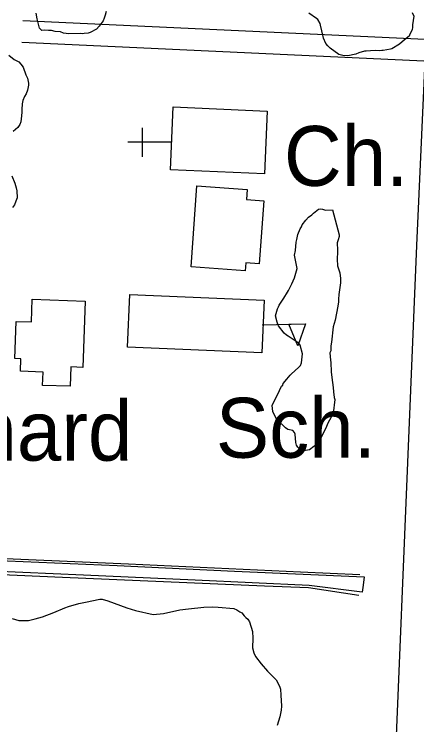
# Model space of a CAD drawing. Extents: x 3677843 to 3715951, y 511991 to 537744.
# Drawn here: x 3693812 to 3694371, y 524461 to 525446 of the extents above; entities that cross this region are included whole.
import ezdxf

# ---------------------------------------------------------------- set-up
doc = ezdxf.new("R2010")
doc.units = 0
for name, color, linetype in [('V-BLDG-IDEN', 7, 'Continuous'), ('V-BLDG-OTLN', 7, 'Continuous'), ('V-ROAD-CNTR', 7, 'Continuous'), ('V-RRAP-FSHR', 7, 'Continuous'), ('V-SITE-OTLN', 7, 'Continuous'), ('V-SITE-OTLN-IDEN', 7, 'Continuous'), ('V-SITE-VEGE', 7, 'Continuous'), ('V-TOPO-SHOR', 7, 'Continuous')]:
    doc.layers.add(name, color=color, linetype=linetype)

msp = doc.modelspace()

# ---------------------------------------------------------------- linework, layer by layer
at = {"layer": 'V-BLDG-OTLN'}
msp.add_line((3694156.62, 525015.2), (3694216.6, 525016.74), dxfattribs=at)
for points in [[(3694057.77, 525095.71), (3694066.02, 525208.25), (3694135.73, 525203.14), (3694134.7, 525189.07), (3694158.62, 525187.32), (3694152.23, 525100), (3694133.94, 525101.34), (3694133.12, 525090.19)], [(3694156.2, 524976.66), (3693969.58, 524984.54), (3693972.66, 525057.48), (3694159.27, 525049.6)], [(3693910.96, 525048.3), (3693907.8, 524956.4), (3693891.08, 524956.97), (3693890.16, 524930.2), (3693851.76, 524931.52), (3693852.39, 524949.92), (3693821.05, 524950.99), (3693821.65, 524968.35), (3693813.3, 524968.64), (3693815.07, 525020.08), (3693836.17, 525019.36), (3693837.26, 525050.83)], [(3694216.6, 525016.74), (3694205.82, 524986.45), (3694193.51, 525016.14)]]:
    msp.add_lwpolyline(points, close=True, dxfattribs=at)
at = {"layer": 'V-ROAD-CNTR'}
for points in [[(3694438.26, 523610.85), (3694392.29, 523695.71), (3694355.89, 523761.39), (3694339.06, 523804.26), (3694326.59, 523855.36), (3694321.7, 523893.17), (3694321.86, 523943.67), (3694324.66, 524023.16), (3694328.91, 524111.65), (3694371.36, 525125.44), (3694418.21, 526169.36), (3694449.93, 526976.4)], [(3694694.4, 525393.26), (3694472.37, 525406.55), (3693824.28, 525436.79)], [(3694692.23, 525363.34), (3694470.78, 525376.6), (3693822.88, 525406.82)]]:
    msp.add_lwpolyline(points, dxfattribs=at)
at = {"layer": 'V-RRAP-FSHR'}
for points in [[(3694291.85, 524668.89), (3694209.71, 524672.61), (3693971.14, 524683.84), (3693746.56, 524693.42), (3693607.22, 524699.07)], [(3693606.63, 524677.46), (3693879.4, 524665.75), (3694159.92, 524653.78), (3694220.73, 524651.43), (3694290.51, 524640.63)]]:
    msp.add_lwpolyline(points, dxfattribs=at)
at = {"layer": 'V-SITE-OTLN'}
for p, q in [((3693989.98, 525288.48), (3693989.98, 525248.48)), ((3694029.98, 525268.48), (3693969.98, 525268.48))]:
    msp.add_line(p, q, dxfattribs=at)
msp.add_lwpolyline([(3694032.91, 525317.4), (3694163.32, 525311.72), (3694159.53, 525224.72), (3694029.12, 525230.41)], close=True, dxfattribs=at)
at = {"layer": 'V-SITE-VEGE'}
for points in [[(3693940.07, 525449.56), (3693938.5, 525444.56), (3693937.45, 525440.68), (3693935.86, 525436.79), (3693930.46, 525429.52), (3693926.67, 525425.04), (3693917.91, 525420.48), (3693915.16, 525419.88), (3693909.65, 525419.24), (3693907.45, 525418.66), (3693904.68, 525419.16), (3693888.13, 525418.88), (3693880.93, 525419.87), (3693876.49, 525421.45), (3693869.31, 525421.88), (3693864.31, 525423.46), (3693859.9, 525423.39), (3693854.92, 525423.86), (3693850.51, 525423.23), (3693847.7, 525426.49), (3693844.17, 525439.69), (3693842.94, 525447.4)], [(3694364.53, 525448.28), (3694366.76, 525443.39), (3694365.22, 525431.38), (3694365.25, 525428.1), (3694364.73, 525424.29), (3694361.51, 525418.26), (3694360.44, 525415.52), (3694353.94, 525410.56), (3694346.9, 525404.5), (3694336.59, 525397.87), (3694334.41, 525397.31), (3694324.61, 525395.59), (3694322.42, 525395.57), (3694319.7, 525395.01), (3694313.7, 525395.5), (3694306.61, 525395.44), (3694300.61, 525394.85), (3694298.43, 525394.83), (3694290.81, 525392.59), (3694286.47, 525390.37), (3694275.58, 525388.1), (3694268.48, 525388.58), (3694263.02, 525390.17), (3694250.95, 525398.8), (3694247.65, 525402.05), (3694244.89, 525405.3), (3694241.56, 525412.91), (3694240.99, 525415.08), (3694237.59, 525430.87), (3694237.03, 525433.05), (3694233.71, 525438.48), (3694232.06, 525440.1), (3694221.09, 525447.65)], [(3693804.7, 525389.35), (3693812.52, 525383.4), (3693818.65, 525380.19), (3693821.47, 525376.93), (3693824.85, 525372.56), (3693828.33, 525362.13), (3693830.63, 525357.2), (3693832.39, 525350.61), (3693832.44, 525347.85), (3693830.9, 525340.64), (3693828.77, 525335.64), (3693826.63, 525331.74), (3693824.51, 525326.18), (3693823.48, 525321.75), (3693823.06, 525314.01), (3693823.13, 525309.6), (3693822.18, 525300.75), (3693821.69, 525296.88), (3693820.1, 525292.98), (3693817.4, 525289.08), (3693810.87, 525283.45)], [(3693809.12, 525222.14), (3693813.16, 525211.71), (3693814.93, 525205.12), (3693816.09, 525201.27), (3693816.26, 525191.34), (3693814.68, 525186.9), (3693812.55, 525181.89), (3693809.85, 525177.98)], [(3693809.65, 524608.09), (3693818.95, 524605.44), (3693832.04, 524605.55), (3693841.29, 524607.81), (3693851.63, 524610.62), (3693867.4, 524616.75), (3693882.62, 524622.88), (3693887.51, 524625.1), (3693902.2, 524629.04), (3693911.46, 524630.75), (3693931.06, 524635.27), (3693934.33, 524635.3), (3693942.54, 524632.64), (3693968.8, 524623.04), (3693980.83, 524619.32), (3694005.42, 524614.07), (3694019.59, 524615.28), (3694042.46, 524620.38), (3694054.44, 524621.57), (3694075.7, 524623.92), (3694087.69, 524624.57), (3694095.33, 524624.08), (3694117.17, 524622.08), (3694121.54, 524620.48), (3694125.38, 524617.78), (3694128.12, 524616.17), (3694131.43, 524611.83), (3694133.63, 524609.67), (3694136.38, 524607.51), (3694139.14, 524603.71), (3694143.07, 524590.11), (3694143.69, 524580.85), (3694143.25, 524567.75), (3694144.94, 524560.68), (3694147.16, 524555.78), (3694154.89, 524545.48), (3694163.7, 524535.19), (3694175.8, 524523.29), (3694180.78, 524514.61), (3694181.9, 524510.25), (3694182.52, 524502.08), (3694183.19, 524486.81), (3694182.69, 524481.35), (3694181.13, 524472.07), (3694177.41, 524460.04)]]:
    msp.add_lwpolyline(points, dxfattribs=at)
msp.add_lwpolyline([(3694253.88, 525174.65), (3694263.44, 525140.36), (3694263.46, 525137.64), (3694261.86, 525133.26), (3694260.81, 525128.89), (3694260.89, 525119.07), (3694260.46, 525104.34), (3694261.05, 525099.44), (3694261.06, 525097.26), (3694264.42, 525087.46), (3694265.03, 525079.83), (3694265.08, 525073.83), (3694263.03, 525057.45), (3694262.54, 525050.91), (3694262.57, 525047.09), (3694261.53, 525041.08), (3694257.87, 525021.96), (3694255.22, 525012.66), (3694252.67, 524991.37), (3694251.62, 524986.45), (3694251.67, 524979.36), (3694250.61, 524976.63), (3694251.24, 524966.27), (3694251.81, 524963), (3694252.46, 524950.46), (3694253.07, 524942.28), (3694254.82, 524928.66), (3694255.42, 524922.67), (3694256.57, 524914.5), (3694257.14, 524911.77), (3694255.11, 524892.67), (3694247.59, 524878.97), (3694245.99, 524874.59), (3694237.95, 524858.16), (3694233.09, 524851.58), (3694228.22, 524846.63), (3694222.26, 524842.21), (3694216.81, 524841.08), (3694213.54, 524841.05), (3694211.35, 524842.12), (3694209.17, 524842.65), (3694205.87, 524845.9), (3694204.21, 524848.61), (3694203.08, 524852.42), (3694202.45, 524863.87), (3694201.33, 524866.04), (3694199.13, 524868.75), (3694192.03, 524870.33), (3694188.74, 524872.48), (3694176.64, 524884.38), (3694173.87, 524889.27), (3694171.1, 524895.24), (3694170.48, 524903.42), (3694180.68, 524924.23), (3694183.35, 524930.26), (3694184.98, 524931.9), (3694185.5, 524934.09), (3694190.91, 524940.14), (3694195.23, 524945.63), (3694197.4, 524947.28), (3694207.14, 524956.09), (3694209.85, 524958.84), (3694210.9, 524962.66), (3694212.44, 524975.22), (3694209.06, 524987.19), (3694207.41, 524989.91), (3694205.21, 524991.53), (3694192.6, 524999.6), (3694190.4, 525001.22), (3694187.11, 525003.92), (3694179.39, 525014.22), (3694177.17, 525019.11), (3694174.91, 525027.82), (3694177.56, 525037.66), (3694179.17, 525040.4), (3694180.25, 525042.59), (3694186.71, 525052.46), (3694191.55, 525060.69), (3694193.17, 525062.88), (3694194.77, 525066.71), (3694197.46, 525072.19), (3694201.21, 525080.4), (3694204.92, 525093.52), (3694204.34, 525097.88), (3694201.49, 525112.04), (3694202.53, 525118.59), (3694203.52, 525130.06), (3694204.58, 525133.88), (3694206.17, 525140.44), (3694209.37, 525148.65), (3694210.98, 525151.39), (3694212.05, 525154.12), (3694216.91, 525160.71), (3694220.7, 525164.56), (3694225.58, 525167.87), (3694227.74, 525170.07), (3694234.79, 525175.58), (3694236.96, 525176.15), (3694240.24, 525175.63), (3694244.61, 525174.57)], close=True, dxfattribs=at)
at = {"layer": 'V-TOPO-SHOR'}
msp.add_lwpolyline([(3693641.33, 524695.51), (3693802.86, 524688.14), (3693955.25, 524681.87), (3694118.19, 524673.81), (3694298.12, 524666.3), (3694296.48, 524654.53), (3694295.13, 524644.87), (3694221.95, 524654.2), (3694063.55, 524661.5), (3693908.76, 524668.28), (3693739.54, 524675.76), (3693640.84, 524680.38)], dxfattribs=at)

# ---------------------------------------------------------------- texts
at = {"layer": 'V-BLDG-IDEN'}
for s, height, p in [('Sch.', 83, (3694092.19, 524831.2)), ('St. Julian Eymard', 82.9998, (3693106.69, 524827.1))]:
    msp.add_text(s, height=height, dxfattribs=at).set_placement(p)
at = {"layer": 'V-SITE-OTLN-IDEN'}
msp.add_text('Ch.', height=83, dxfattribs=at).set_placement((3694186.71, 525208.05))

doc.saveas('drawing.dxf')
